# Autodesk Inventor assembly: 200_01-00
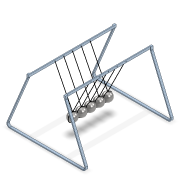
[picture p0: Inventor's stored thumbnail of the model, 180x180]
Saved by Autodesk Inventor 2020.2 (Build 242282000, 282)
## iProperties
Manager: www.cadconsulting.pl
Company: Fabian Stasiak CAD Consulting
Created: 2020-03
Part Number: 200_01-00
Document SubType Name: Assembly
Designer: F.Stasiak
Catalog Web Link: www.expertbooks.pl
Author: F.Stasiak
Subject: Zbiór ćwiczeń. Autodesk Inventor 2020. Kurs Professional
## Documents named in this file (3)
- C:\2020_Kurs_Professional\R3 Dynamika\200_01-00.iam
- C:\2020_Kurs_Professional\R3 Dynamika\Komponenty_dyn\200_01_Kulka.ipt
- C:\2020_Kurs_Professional\R3 Dynamika\Komponenty_dyn\200_02_Ramka.ipt
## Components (6 placed, 2 different names)
1. 200_02_Ramka:1 — Zestawiające:1, Zestawiające:2, Zestawiające:3, Zestawiające:4, Zestawiające:5, Zestawiające:6, Zestawiające:7, Zestawiające:8, Zestawiające:9, Zestawiające:10
2. 200_01_Kulka:1 — Zestawiające:1, Zestawiające:2
3. 200_01_Kulka:2 — Zestawiające:3, Zestawiające:4
4. 200_01_Kulka:3 — Zestawiające:5, Zestawiające:6
5. 200_01_Kulka:4 — Zestawiające:7, Zestawiające:8
6. 200_01_Kulka:5 — Zestawiające:9, Zestawiające:10
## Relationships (10: Mate 10)
- Zestawiające:1 [Mate]: 200_02_Ramka:1 ↔ 200_01_Kulka:1
- Zestawiające:2 [Mate]: 200_02_Ramka:1 ↔ 200_01_Kulka:1
- Zestawiające:3 [Mate]: 200_02_Ramka:1 ↔ 200_01_Kulka:2
- Zestawiające:4 [Mate]: 200_02_Ramka:1 ↔ 200_01_Kulka:2
- Zestawiające:5 [Mate]: 200_02_Ramka:1 ↔ 200_01_Kulka:3
- Zestawiające:6 [Mate]: 200_02_Ramka:1 ↔ 200_01_Kulka:3
- Zestawiające:7 [Mate]: 200_02_Ramka:1 ↔ 200_01_Kulka:4
- Zestawiające:8 [Mate]: 200_02_Ramka:1 ↔ 200_01_Kulka:4
- Zestawiające:9 [Mate]: 200_02_Ramka:1 ↔ 200_01_Kulka:5
- Zestawiające:10 [Mate]: 200_02_Ramka:1 ↔ 200_01_Kulka:5
